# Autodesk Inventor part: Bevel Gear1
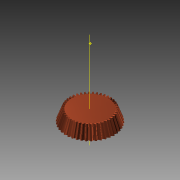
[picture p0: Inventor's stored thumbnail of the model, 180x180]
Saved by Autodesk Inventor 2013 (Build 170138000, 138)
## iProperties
Created: 2008-07
Part Number: Bevel Gear1
Material: Steel, Mild
Document SubType Name: Modeling
Designer: tangg
Categories: <?xml version="1.0" encoding="UTF-16"?> <MemberInstance><Categories><FamilyTemplate><FamilyTemplateParameter ValueType="xs:double" Id="1" ObjectReferenceKey="da
Mass: 60.9118 g
Surface Area: 34.3074 cm^2
Volume: 7.7496 cm^3
Density: 7.86 g/cm^3
CustomPartVersion: 1
Author: tangg
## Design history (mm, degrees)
node "Top Point"
node "Mesh Plane2"
sketch "Teeth Body Sketch"
  geometry: L1 (0, 0)-(13.905, -43.186); L2 (13.905, -43.186)-(15.362, -42.687); L3 (15.362, -42.687)-(0, 0); L4 (14.7, -42.914)-(0, 0); L5 (11.453, -35.569)-(12.653, -35.158); L6 (13.905, -43.186)-(11.453, -35.569); L7 (15.362, -42.687)-(12.653, -35.158); L8 (0, -51.823)-(0, 8.637) reference; L9 (0, -42.914)-(15.362, -42.914)
  constraints: 16 end point, 4 point on line, 3 perpendicular, 2 collinear, 1 horizontal alignment, 1 vertical alignment
  dimensions: "d0" = 29.4 diameter of L4.start L8 (= da_de); "d1" = 27.81066 diameter of L1.end L8 (= da_dfe); "d2" = 30.72445 diameter of L2.end L8 (= da_dae); "d3" = 8 distance between parallel lines of L2 L5 (= da_b); "d4" = 42.68672 vertical distance of L2.end L1.start (= da_ve)
revolve "Teeth Body" sketch "Teeth Body Sketch" stored, may be unused: angle "d5" = 90 deg
node "Start Point"
node "Tooth Plane"
sketch "Start Sketch"
  geometry: L1 (0, -35.958)-(0, 11.125) reference; L2 (-0.217, -0.185)-(0.217, -0.185); A1 r 5.975 centre (-6.038, -1.531) between (-0.217, -0.185) and (-1.189, 1.96); A2 r 5.975 centre (6.038, -1.531) between (1.189, 1.96) and (0.217, -0.185); A3 r 16.701 centre (0, -14.699) between (1.189, 1.96) and (-1.189, 1.96); 1 further point
  constraints: 6 point on circle, 3 centre point, 3 symmetric about line, 2 end point, 1 coincident, 1 perpendicular, 1 other
  dimensions: "d7" = 5.97468 radius of A1 (= fd_rr); "d8" = 6.03788 horizontal distance of point (0, -14.699) A1.centre (= fd_x); "d9" = 13.16739 vertical distance of point (0, -14.699) A1.centre (= fd_y); "d57" = 16.70053 radius of A3 (= 0.5 x fd_dva + 0.3 x da_he); "d58" = 14.51373 distance from line of A3.centre L2 (= 0.5 x fd_dva - 1.12 x da_he)
node "End Point"
  node "End Plane"
sketch "3D Sketch Right"
  node "Helical Curve Right" dims "d65" = 286.15708 (computed from da_dm, da_delta, da_beta), "d66" = 31.5, "d67" = 29.4 (= da_de), "d68" = -3.30022 (= -da_delta), "d69" = 7.64113 (computed from fd_loft, da_delta)
node "End Plane Right"
sketch "End Sketch Right"
  geometry: L1 (0, -17.689)-(0, 5.893) reference; L2 (-0.178, -0.828)-(0.178, -0.828); A1 r 4.917 centre (-4.969, -1.936) between (-0.178, -0.828) and (-0.978, 0.937); A2 r 4.917 centre (4.969, -1.936) between (0.978, 0.937) and (0.178, -0.828); A3 r 13.744 centre (0, -12.772) between (0.978, 0.937) and (-0.978, 0.937); 1 further point
  constraints: 6 point on circle, 3 centre point, 3 symmetric about line, 2 end point, 1 coincident, 1 perpendicular, 1 other
  dimensions: "d70" = 4.96882 horizontal distance of A3.centre A1.centre (computed from fd_x, fd_ratio); "d71" = 10.83599 vertical distance of point (0, -12.772) A1.centre (computed from fd_y, fd_ratio); "d72" = 4.91681 radius of A1 (computed from fd_rr, fd_ratio); "d73" = 11.94395 distance from line of point (0, -12.772) L2 (computed from d58, fd_ratio); "d74" = 13.74356 radius of A3 (computed from d57, fd_ratio)
feature "Loft Right" sketch "End Sketch Right" dims "d75" = 0, "d76" = 90 deg, "d77" = 0, "d78" = 90 deg, "d79" = 0, "d80" = 90 deg, "d85" = 20, "da_teethtype" = 0 [user parameter]
sketch "3D Sketch Left"
  node "Helical Curve Left" dims "d26" = 286.15708 (computed from da_dm, da_delta, da_beta), "d27" = 7.64113 (computed from fd_loft, da_delta), "d28" = 29.4 (= da_de), "d29" = -3.30022 (= -da_delta)
node "End Plane Left"
sketch "End Sketch Left" dims "d56" = 11.97023 (derived)
  geometry: L1 (0, -33.711)-(0, 11.326) reference; L2 (-0.178, -0.827)-(0.178, -0.827); A1 r 4.917 centre (-4.969, -1.935) between (-0.178, -0.827) and (-0.978, 0.938); A2 r 4.917 centre (4.969, -1.935) between (0.978, 0.938) and (0.178, -0.827); A3 r 13.744 centre (0, -12.771) between (0.978, 0.938) and (-0.978, 0.938); 2 further points; 1 other entity
  constraints: 6 point on circle, 3 centre point, 3 symmetric about line, 2 end point, 1 coincident, 2 other
  dimensions: "d30" = 4.91681 radius of A1 (computed from fd_rr, fd_ratio); "d31" = 4.96882 horizontal distance of point (0, -12.771) A1.centre (computed from fd_x, fd_ratio); "d32" = 10.83599 vertical distance of A1.centre point (0, -12.771) (computed from fd_y, fd_ratio); "d61" = 13.74356 radius of A3 (computed from d57, fd_ratio); "d62" = 11.94395 distance from line of point (0, -12.771) L2 (computed from d58, fd_ratio)
feature "Loft Left" sketch "End Sketch Left" dims "d35" = 0, "d37" = 0, "d39" = 0, "d40" = 90 deg, "d63" = 90 deg, "d64" = 90 deg, "d84" = 10, "da_teethtype" = 0 [user parameter]
sketch "Body Sketch"
  geometry: L1 (0, -44.709)-(0, -34.046) reference; L2 (13.905, -43.186)-(11.453, -35.569) reference; L3 (11.453, -35.569)-(0, -35.569); L4 (13.905, -43.186)-(0, -43.186)
  constraints: 4 end point, 2 perpendicular, 2 point on line
revolve "Fix Body" sketch "Body Sketch" stored, may be unused: angle "d46" = 90 deg
sketch "Sketch6"
  geometry: L1 (14.7, -42.914)-(0, 0) reference; L2 (0, -51.496)-(0, 8.583) reference
feature "Pitch Diameter" sketch "Sketch6" dims angle "d47" = 90 deg
body "Solid1"
feature "Loft" dims "d17" = 0, "d18" = 90 deg, "d19" = 0, "d20" = 90 deg, "d89" = 0, "da_teethtype" = 0 [user parameter]
pattern_circular "Circular Pattern" dims angle "d22" = 360 deg, "d88" = 0, "da_teethtype" = 0 [user parameter]
pattern_circular "Circular Pattern Right" dims angle "d82" = 360 deg, "da_teethtype" = 0 [user parameter]
pattern_circular "Circular Pattern Left" dims angle "d42" = 360 deg, "da_teethtype" = 0 [user parameter]
sketch "End Sketch"
  geometry: L1 (0, -34.035)-(0, 10.392) reference; L2 (-0.178, 0.012)-(0.178, 0.012); A1 r 4.917 centre (-4.969, -1.096) between (-0.178, 0.012) and (-0.978, 1.777); A2 r 4.917 centre (4.969, -1.096) between (0.978, 1.777) and (0.178, 0.012); A3 r 13.744 centre (0, -11.932) between (0.978, 1.777) and (-0.978, 1.777); 1 further point
  constraints: 6 point on circle, 3 centre point, 3 symmetric about line, 2 end point, 1 coincident, 1 other
  dimensions: "d12" = 4.91681 radius of A1 (computed from fd_rr, fd_ratio); "d15" = 4.96882 horizontal distance of A1.centre point (0, -11.932) (computed from fd_x, fd_ratio); "d16" = 10.83599 vertical distance of A1.centre point (0, -11.932) (computed from fd_y, fd_ratio); "d59" = 13.74356 radius of A3 (computed from d57, fd_ratio); "d60" = 11.94395 distance from line of A3.centre L2 (computed from d58, fd_ratio)
body "Srf1"
other parameters: "da_b" = 8 [user parameter; used in 2 equation terms], "da_de" = 29.4 [user parameter; used in 4 equation terms], "da_dae" = 30.72445 [user parameter; used in 2 equation terms], "da_dfe" = 27.81066 [user parameter; used in 1 equation term], "da_le" = 45.36148 [user parameter; used in 1 equation term], "da_omega" = 45 deg [user parameter], "da_beta" = 0 [user parameter; used in 2 equation terms], "da_delta" = 3.30022 [user parameter; used in 8 equation terms], "da_alpha" = 20 deg [user parameter; used in 1 equation term], "da_he" = 1.54 [user parameter; used in 4 equation terms], "da_ve" = 42.68672 [user parameter; used in 1 equation term], "fd_dv" = 31.07706 (computed from da_de, da_delta) [user parameter; used in 1 equation term], "fd_dva" = 32.47706 (computed from da_dae, da_delta) [user parameter; used in 3 equation terms], "fd_dvb" = 29.20289 (computed from fd_dv, da_alpha) [user parameter; used in 2 equation terms], "da_zv" = 443.95805 [user parameter; used in 1 equation term], "fd_loft" = 8.077 (= da_b + 0.05 x da_he) [user parameter; used in 4 equation terms], "fd_ratio" = 8.22941 (computed from da_le, fd_loft) [user parameter; used in 15 equation terms], "fd_rr" = 5.97468 (computed from fd_dd, fd_dvb) [user parameter; used in 6 equation terms], "fd_angle" = 0.35382 (computed from da_zv) [user parameter; used in 4 equation terms], "fd_x1" = 0.54966 (computed from da_dvw, fd_angle) [user parameter; used in 1 equation term], "fd_y1" = 15.52881 (computed from da_dvw, fd_angle) [user parameter; used in 1 equation term], "fd_x2" = 5.48821 (computed from fd_rr, fd_angle2, fd_angle) [user parameter; used in 1 equation term], "fd_y2" = 2.36142 (computed from fd_rr, fd_angle2, fd_angle) [user parameter; used in 1 equation term], "fd_x" = 6.03788 (= fd_x1 + fd_x2) [user parameter; used in 4 equation terms], "fd_y" = 13.16739 (= fd_y1 - fd_y2) [user parameter; used in 4 equation terms], "fd_angle2" = 3.70945 (computed from fd_dvb, fd_dd) [user parameter; used in 2 equation terms], "fd_dd" = 31.55306 (= fd_dva - 0.6 x da_he) [user parameter; used in 2 equation terms], "da_dvw" = 31.07706 [user parameter; used in 2 equation terms], "d11" = -8.077 (= -fd_loft), "da_dm" = 26.80749 [user parameter; used in 2 equation terms], "da_x" = 0 [user parameter], "da_m" = 0.7 [user parameter], "d51" = 0.748 (computed from da_z)
